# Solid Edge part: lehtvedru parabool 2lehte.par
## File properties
Title: Lehtvedru parabool 2 lehte
Author: Kadik
Template: Iso Part.par
Last saved by: kai
Revision: 7
Application: Solid Edge
Density: 7833,000 kg/m^3
Accuracy: 0,990
Face Style: Steel
Fill Style: ANSI32(Steel)
Virtual Style: Machined steel
Coef. of Thermal Exp: 1.3e-05
Thermal Conductivity: 32.0
Specific Heat: 481.0
Modulus of Elasticity: 199947953000.0
Poisson's Ratio: 0.29
Yield Stress: 262000766.0
Ultimate Stress: 358527364.0
Elongation: 0.0
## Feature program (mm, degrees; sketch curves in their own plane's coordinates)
sketch for "unnamed Protrusion 1" #1 plane through (0, 0, 0) normal (0, -1, 0) x-axis (1, 0, 0)
  line (764, -21) -> (764, -13)
  arc centre (371.5, -955) radius 1020.5 from (371.5, 65.5) to (764, -13) cw
  arc centre (371.5, -1658.6049) radius 1724.1049 from (371.5, 65.5) to (0, 25) ccw
  arc centre (5.8087, -1.3246) radius 26.9578 from (0, 25) to (-20.4744, 4.6688) ccw
  arc centre (371.5, -2303.4407) radius 2353.9407 from (371.5, 50.5) to (0, 21) ccw
  arc centre (371.5, -1062.5664) radius 1113.0664 from (371.5, 50.5) to (764, -21) cw
sketch for "unnamed Protrusion 1" #2 plane through (0, 0, 0) normal (0, -1, 0) x-axis (1, 0, 0)
  circle centre (0, 0) radius 14
extrude "unnamed Protrusion 1" add finite 50 symmetric
fillet "Round_1" radius 2
fillet "Round_2" radius 5
fillet "Round_3" radius 0.5
sketch for "ExtrudedProtrusion_2" plane through (0, 0, 51.9645) normal (0, 0, 1) x-axis (1, 0, 0)
  circle centre (371.5, 0) radius 6
extrude "ExtrudedProtrusion_2" add finite 6.46 along -normal
fillet "unnamed Round 1"
sketch for "unnamed Protrusion 2" plane through (371.5, -25, 22.25) normal (0, -1, 0) x-axis (0, 0, 1)
extrude "unnamed Protrusion 2" add to key point along -normal
sketch for "ExtrudedProtrusion_4" plane through (371.5, 0, 45.5045) normal (0, 0, -1) x-axis (1, 0, 0)
extrude "ExtrudedProtrusion_4" add finite 44 along -normal
sketch for "unnamed Protrusion 3" plane through (371.5, 0, 89.5045) normal (0, 0, 1) x-axis (1, 0, 0)
extrude "unnamed Protrusion 3" add finite 5 along +normal
chamfer "Chamfer_1" setback 1
thread "unnamed Thread 1"
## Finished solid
Body 1: solid body, 38 faces, 105 edges, 66 vertices.
  Faces by surface: plane 24, cylinder 13, cone 1
  Edges by curve: line 53, circle 38, ellipse 12, intersection 2
Bounding box of the edges (mm): 785.000 x 50.000 x 115.504, from (-21, -25, -21) to (764, 25, 94.5045).
Cylindrical faces by radius (mm): R4 x1, R6 x1, R14 x1, R21 x1, R26.9578 x1, R922.5638 x1, R1020.5 x1, R1020.55 x1, R1113.0664 x1, R1418.8639 x1, R1724.1049 x1, R1724.1549 x1, R2353.9407 x1
Conical faces (half-angle, radius in mm at the cone's reference point): 45 deg R4 x1
Planar faces by outward normal: +x 2, +y 3, +z 2, -x 1, -y 3, -z 3, oblique 10
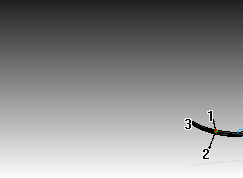
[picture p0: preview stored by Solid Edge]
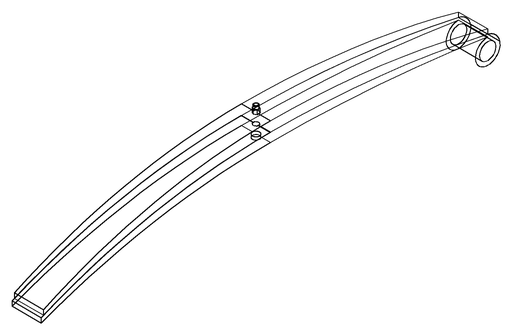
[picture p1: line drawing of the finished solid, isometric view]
